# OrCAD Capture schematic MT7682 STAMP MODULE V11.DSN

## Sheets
1 10_BB_RF: size C; title: MT7682 Stamp Module; rev: 1.1; company: MediaTek Inc.; note: 10_BB_RF
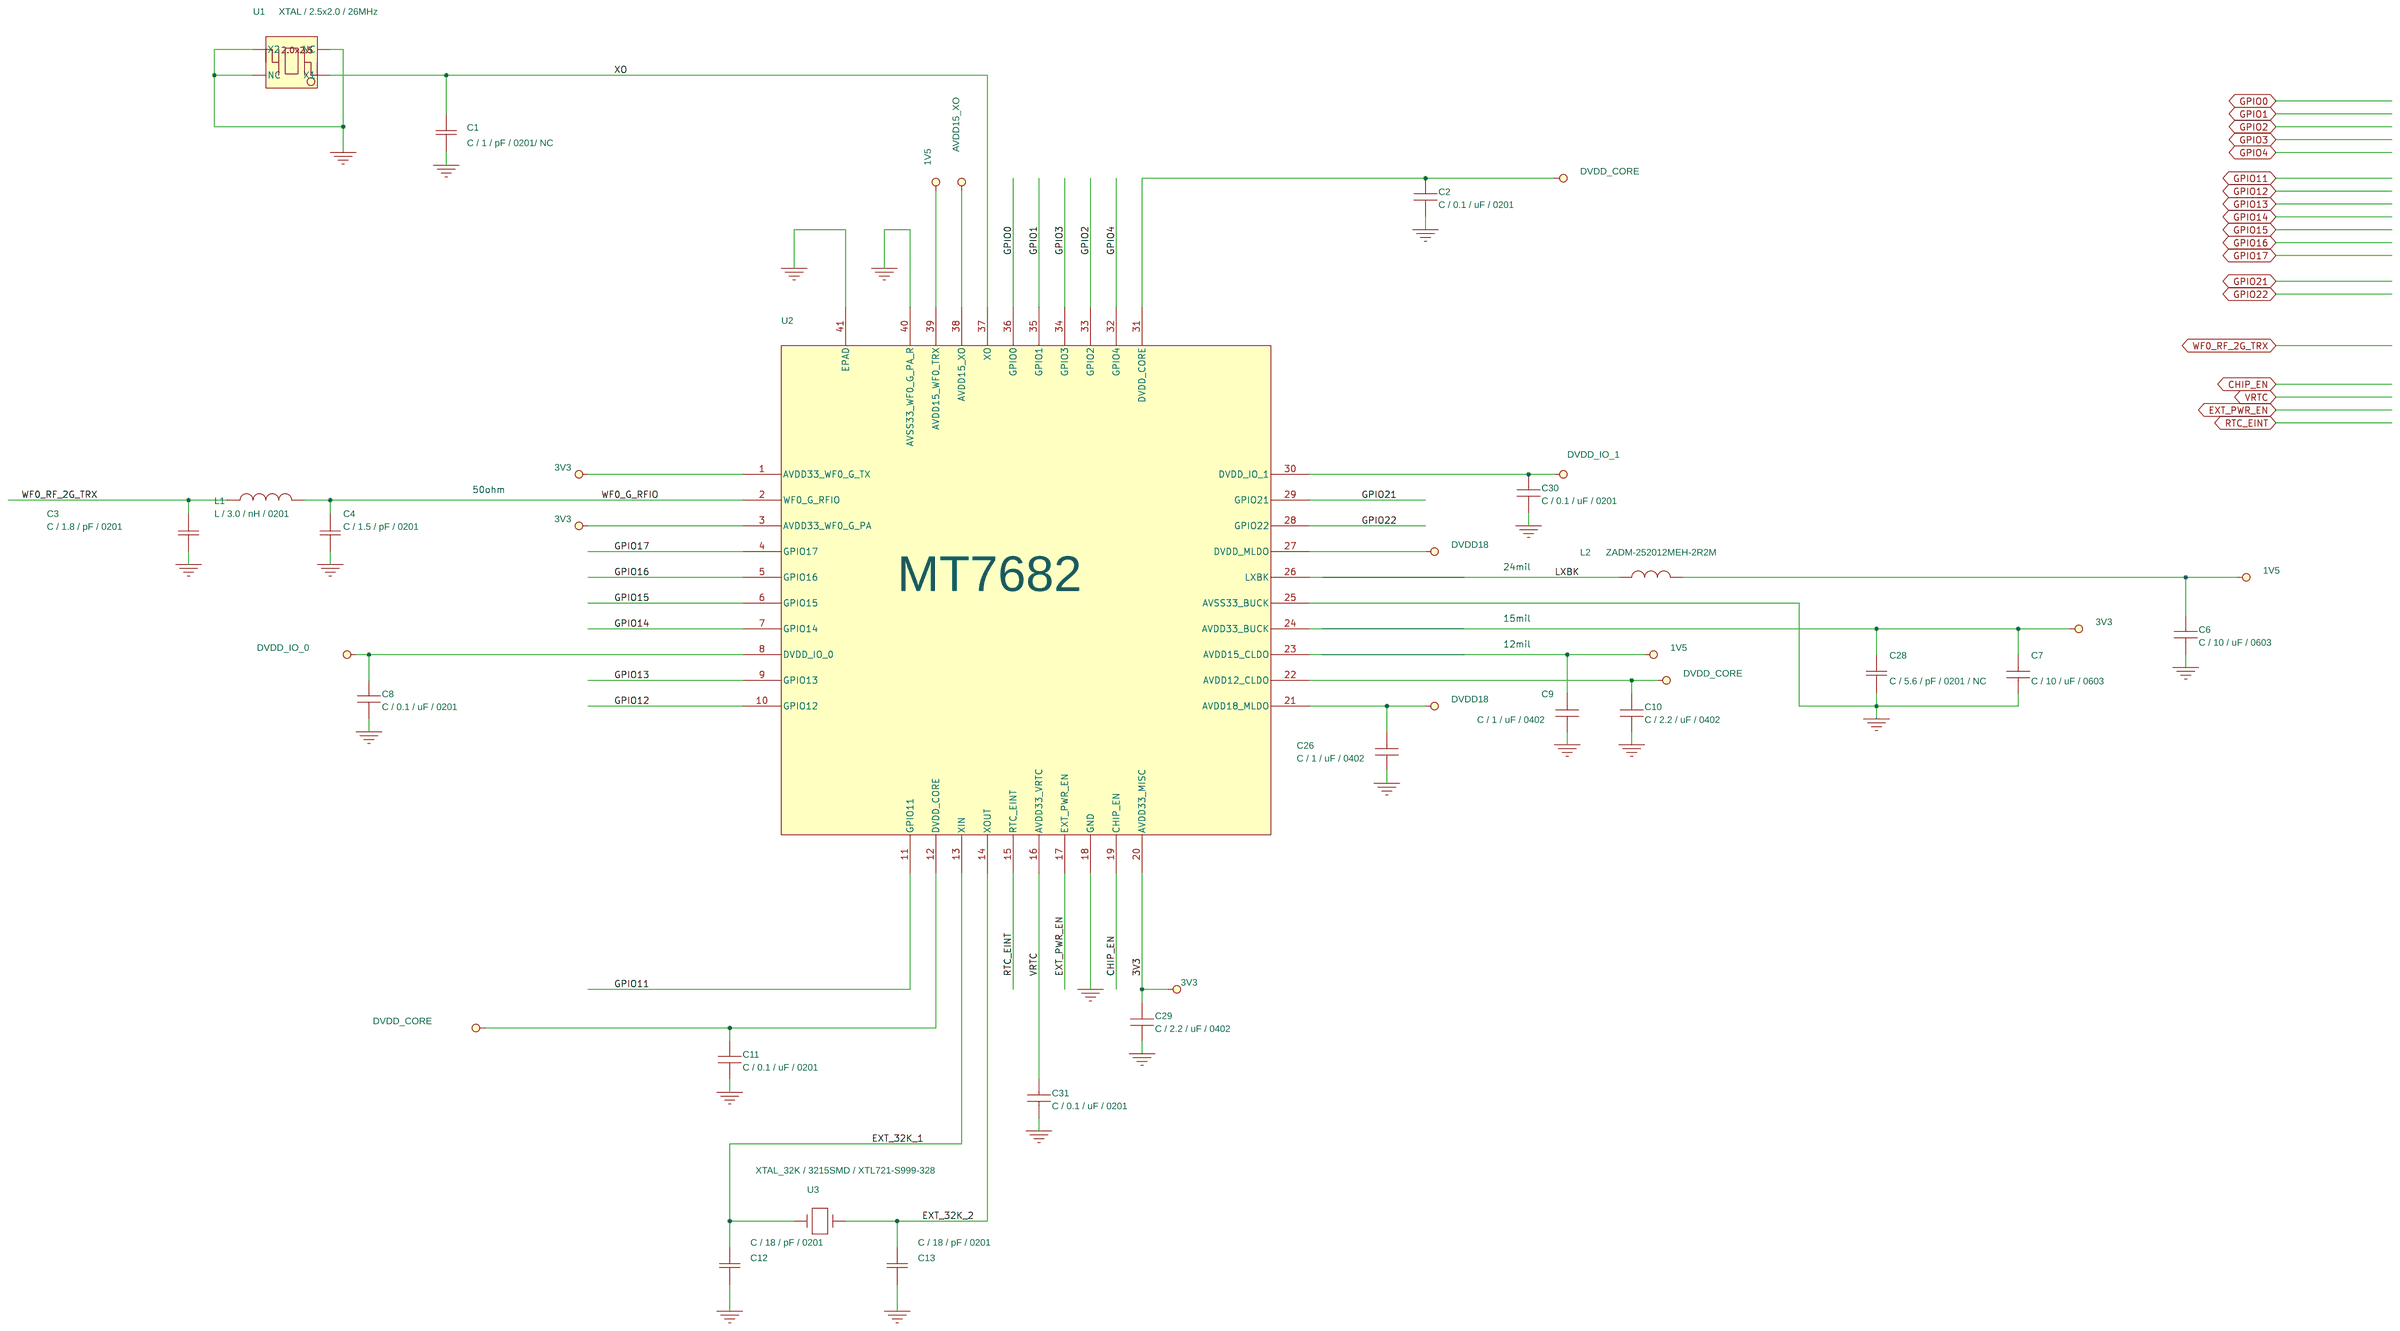
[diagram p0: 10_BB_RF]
2 20_RF Antenna and Connector: size C; note: 20_RF Antenna and Connector
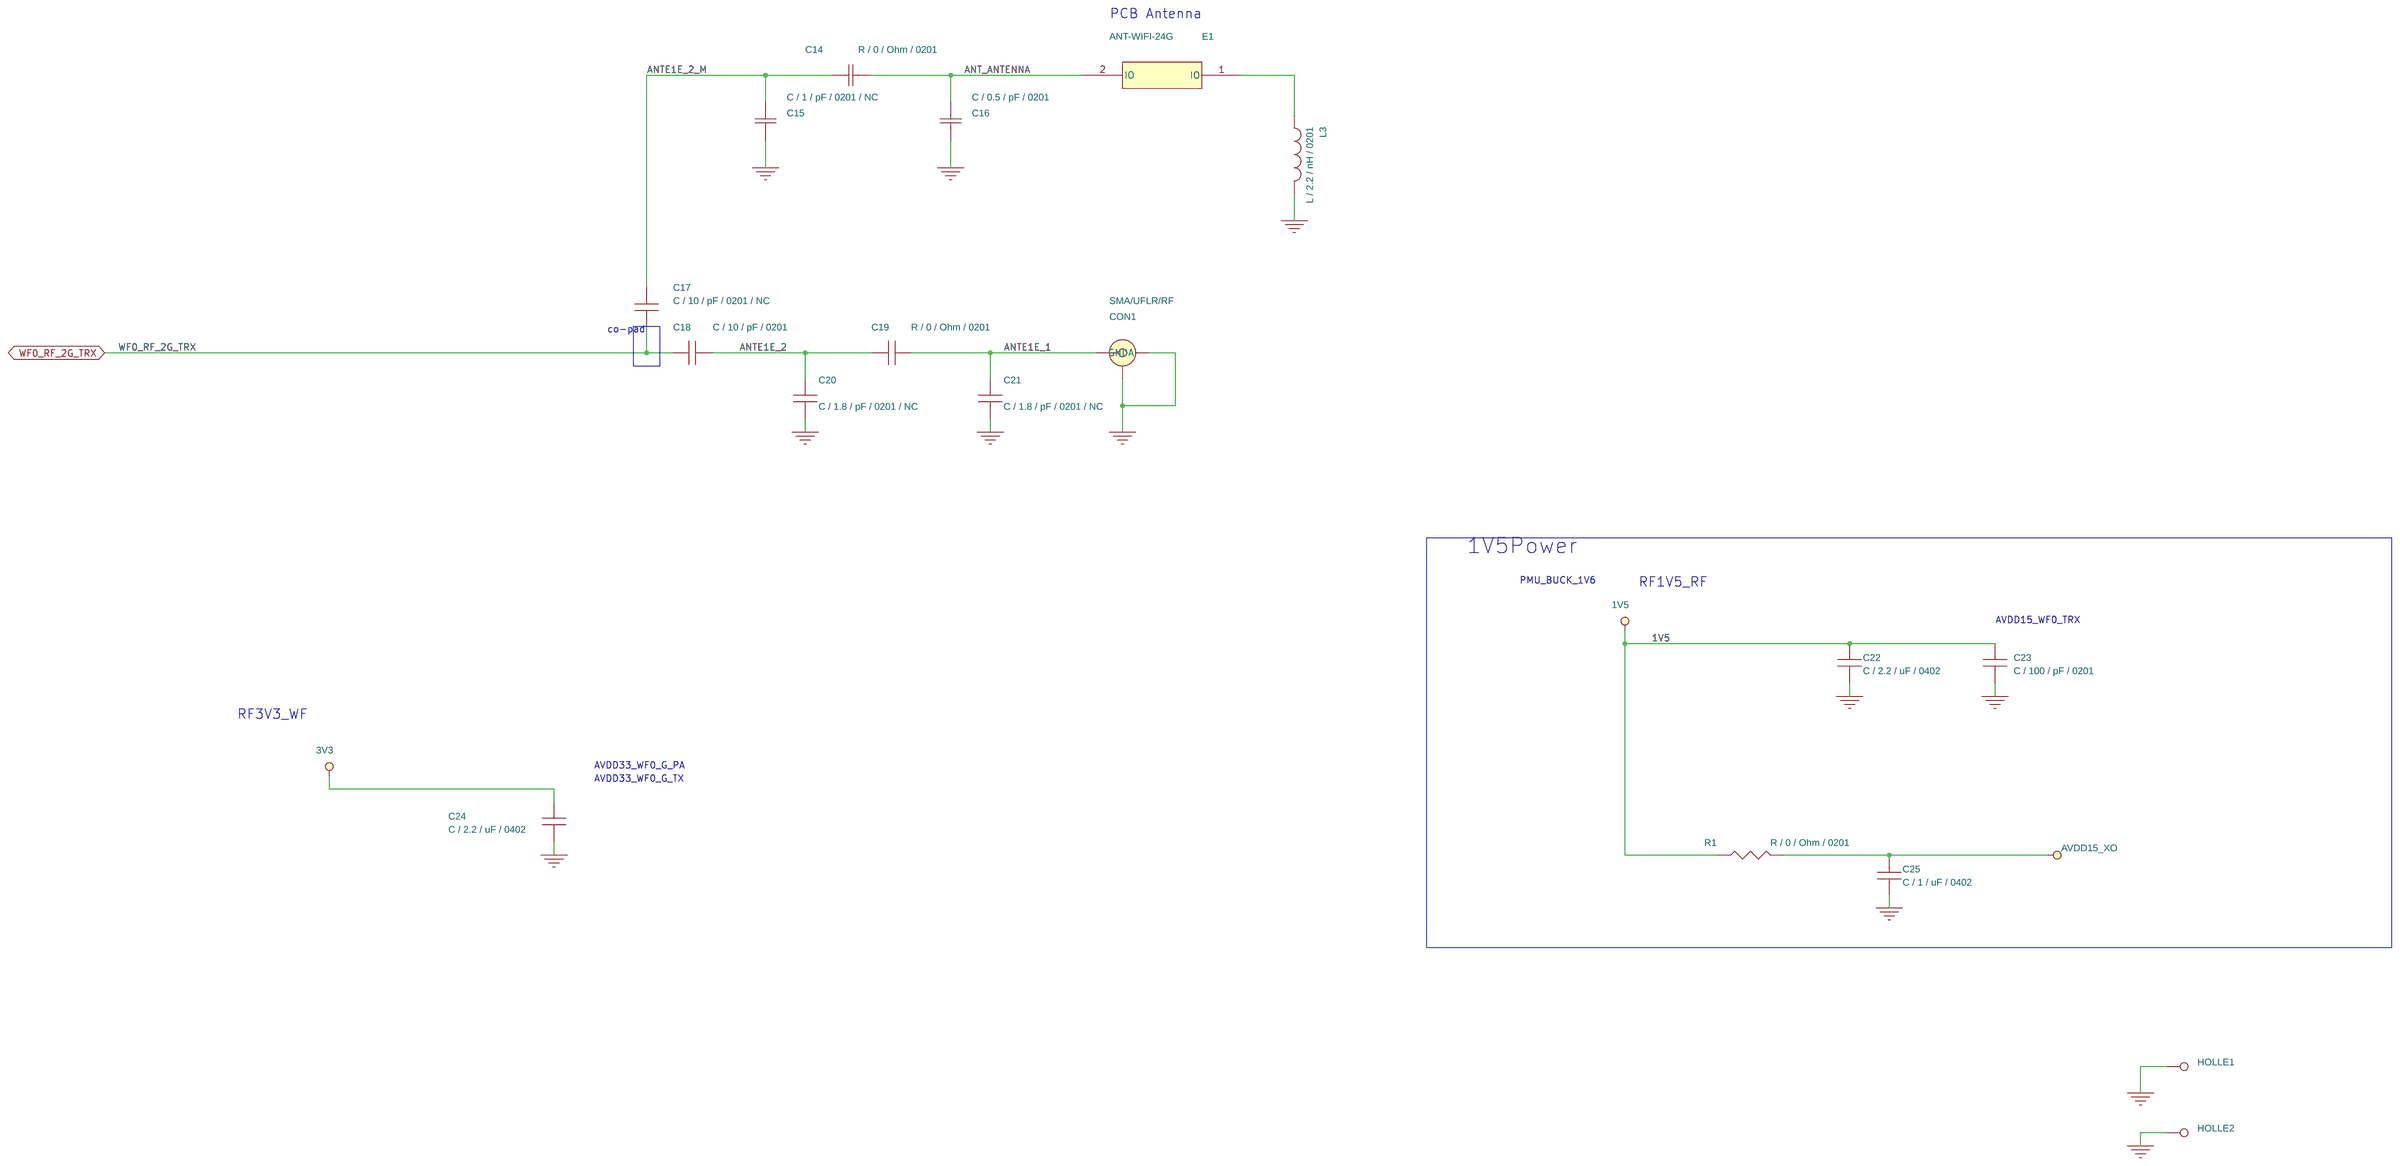
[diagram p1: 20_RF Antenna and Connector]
3 21_Strap and Module: size C; note: 21_Strap and Module
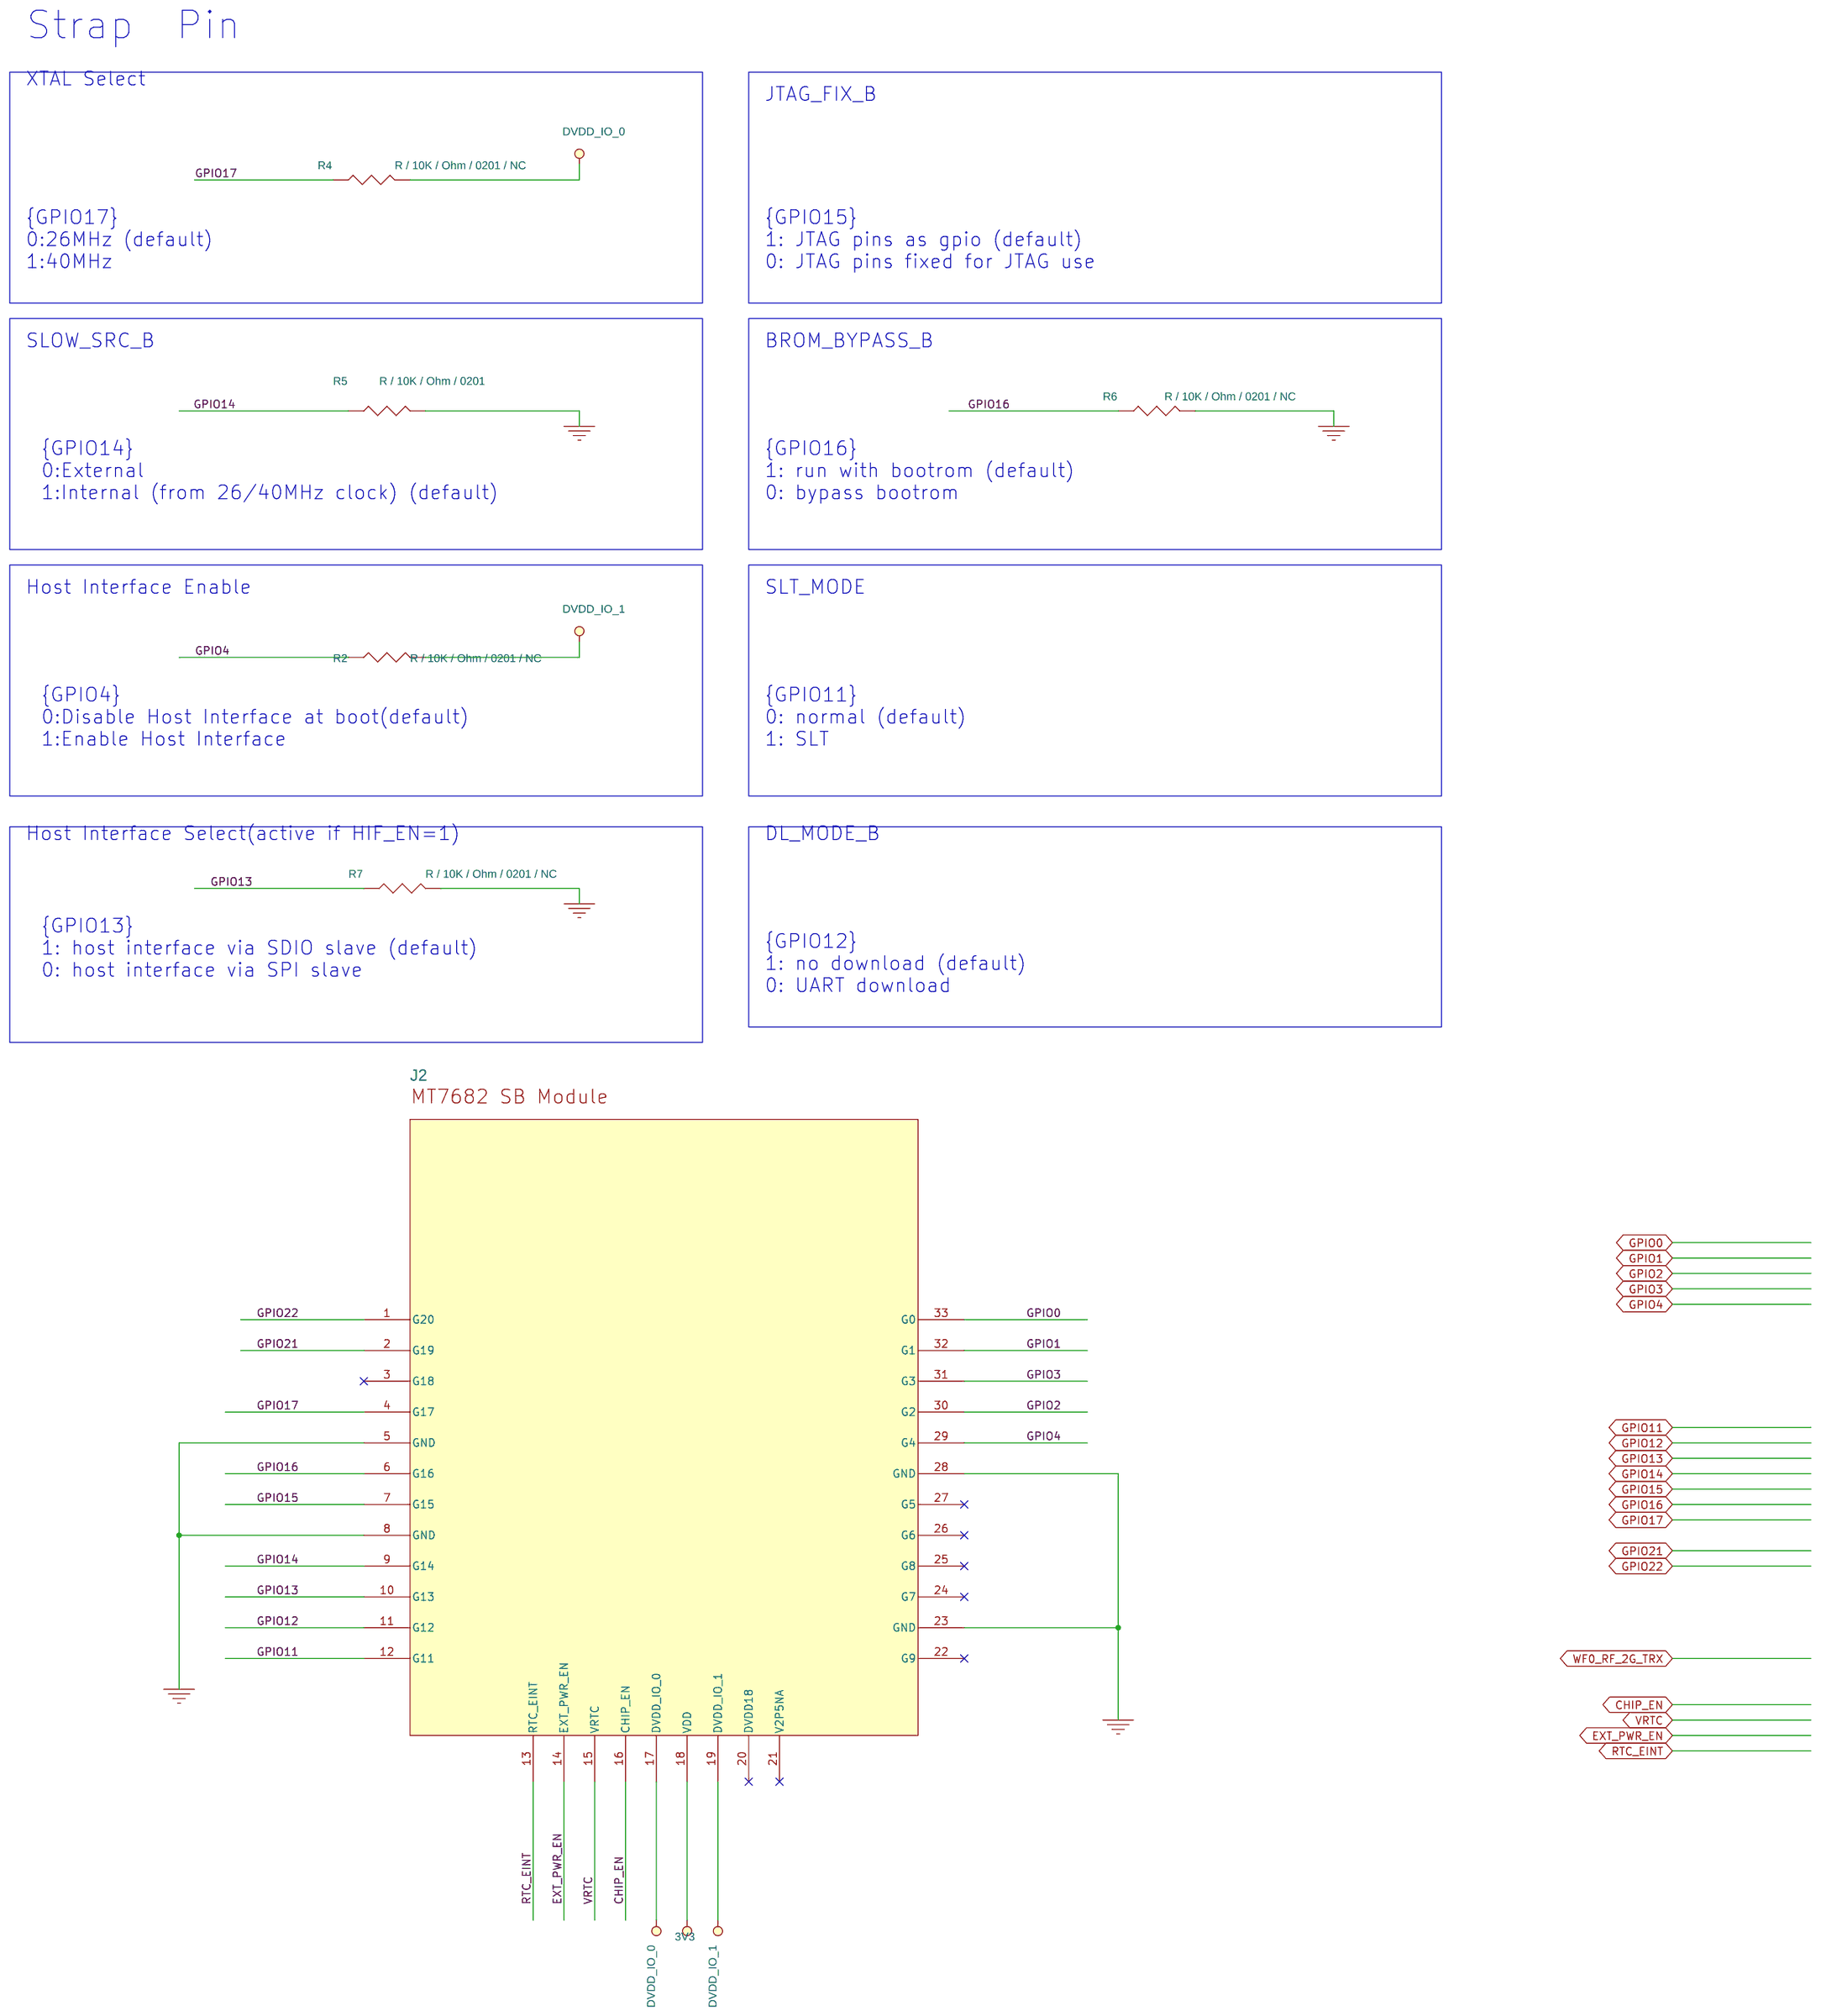
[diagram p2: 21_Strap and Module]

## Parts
sheet 10_BB_RF
C1  C / 1 / pF / 0201/ NC  [C0201]
C2  C / 0.1 / uF / 0201  [C0201]
C3  C / 1.8 / pF / 0201  [C0201]
C4  C / 1.5 / pF / 0201  [C0201]
C6  C / 10 / uF / 0603  [C0603]
C7  C / 10 / uF / 0603  [C0603]
C8  C / 0.1 / uF / 0201  [C0201]
C9  C / 1 / uF / 0402  [C0402]
C10  C / 2.2 / uF / 0402  [C0402]
C11  C / 0.1 / uF / 0201  [C0201]
C12  C / 18 / pF / 0201  [C0201]
C13  C / 18 / pF / 0201  [C0201]
C26  C / 1 / uF / 0402  [C0402]
C28  C / 5.6 / pF / 0201 / NC  [C0201]
C29  C / 2.2 / uF / 0402  [C0402]
C30  C / 0.1 / uF / 0201  [C0201]
C31  C / 0.1 / uF / 0201  [C0201]
L1  L / 3.0 / nH / 0201  [L0201]
L2  ZADM-252012MEH-2R2M  [L/IND/SMD/VLS252012E]
U1  XTAL / 2.5x2.0 / 26MHz  [CRYS/SMD/2.5X2.0/CT2520DB/KYOCERA]
U2  MT7682  [MT7682/SQFN40/P0.4/SMD/5X5]
U3  XTAL_32K / 3215SMD / XTL721-S999-328  [RTC/SMD/2P/3.2X1.5]
sheet 20_RF Antenna and Connector
C14  R / 0 / Ohm / 0201  [C0201]
C15  C / 1 / pF / 0201 / NC  [C0201]
C16  C / 0.5 / pF / 0201  [C0201]
C17  C / 10 / pF / 0201 / NC  [C0201]
C18  C / 10 / pF / 0201  [C0201]
C19  R / 0 / Ohm / 0201  [C0201]
C20  C / 1.8 / pF / 0201 / NC  [C0201]
C21  C / 1.8 / pF / 0201 / NC  [C0201]
C22  C / 2.2 / uF / 0402  [C0402]
C23  C / 100 / pF / 0201  [C0201]
C24  C / 2.2 / uF / 0402  [C0402]
C25  C / 1 / uF / 0402  [C0402]
CON1  SMA/UFLR/RF  [COAXIAL/SMD/CON/V/I-PEX]
E1  ANT-WIFI-24G  [ANT/2P/SMD/MT7682/RF_1]
HOLLE1  TP-SMD  [HOLE/PTH/R1X1.5D0.6]
HOLLE2  TP-SMD  [HOLE/PTH/R1X1.5D0.6]
L3  L / 2.2 / nH / 0201  [L0201]
R1  R / 0 / Ohm / 0201  [R0201]
sheet 21_Strap and Module
J2  pin to pin module  [MODULE/33P/SMD/MT7682]
R2  R / 10K / Ohm / 0201 / NC  [R0201]
R4  R / 10K / Ohm / 0201 / NC  [R0201]
R5  R / 10K / Ohm / 0201  [R0201]
R6  R / 10K / Ohm / 0201 / NC  [R0201]
R7  R / 10K / Ohm / 0201 / NC  [R0201]

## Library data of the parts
C1 C3 C4 C12-C16 C28 = CAP_0402
C2 C6 C8 C11 C22-C24 C30 C31 = CAPACITOR_NON-POL: PART_NUMBER: C21-0402M104Y1EWLS; PART_TYPE: C21
C7 C9 C10 C25 C26 C29 = C_0402
L1 L3 = INDUCTOR: PART_NUMBER: L42-0201S3N320ACX0; PART_TYPE: L42
L2 = L_2.5*2.0
U1 = XTAL_2.5
U2 = MT7662E-20121128_11
U3 = XTAL_49_U-SMD
C17-C19 = CAPACITOR_NON-POL: PART_NUMBER: C21-0201C3R9C1HTDK; PART_TYPE: C21
C20 = CAPACITOR_NON-POL: PART_NUMBER: C21-0201BR30C1HTDK; PART_TYPE: C21
C21 = CAPACITOR_NON-POL: PART_NUMBER: C21-0201BR30C1HTDK
CON1 = SMA_UFLR
E1 = ANT-25G-R-CB_0
HOLLE1 HOLLE2 = TP-SMD
R1 R2 R4-R7 = RESISTOR: PART_NUMBER: R31-0201J1003FWLS0; PART_TYPE: R31
J2 = S500_6

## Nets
1V5: C6.1 C9.2 C22.1 C23.1 L2.2 R1.2 U2.23(AVDD15_CLDO) U2.39(AVDD15_WF0_TRX)
3V3: C7.2 C24.1 C28.1 C29.2 J2.18(VDD) U2.1(AVDD33_WF0_G_TX) U2.3(AVDD33_WF0_G_PA) U2.20(AVDD33_MISC) U2.24(AVDD33_BUCK)
AVDD15_XO: C25.2 R1.1 U2.38(AVDD15_XO)
DVDD18: C26.2 U2.21(AVDD18_MLDO) U2.27(DVDD_MLDO)
DVDD_CORE: C2.1 C10.2 C11.1 U2.12(DVDD_CORE) U2.22(AVDD12_CLDO) U2.31(DVDD_CORE)
DVDD_IO_0: C8.1 J2.17(DVDD_IO_0) R4.1 U2.8(DVDD_IO_0)
DVDD_IO_1: C30.1 J2.19(DVDD_IO_1) R2.1 U2.30(DVDD_IO_1)
GND: C1.2 C2.2 C3.1 C4.1 C6.2 C7.1 C8.2 C9.1 C10.1 C11.2 C12.2 C13.2 C15.2 C16.2 C20.2 C21.2 C22.2 C23.2 C24.2 C25.1 C26.1 C28.2 C29.1 C30.2 C31.2 CON1.2 CON1.3(GNDA) HOLLE1.1 HOLLE2.1 J2.5(GND) J2.8(GND) J2.23(GND) J2.28(GND) L3.1 R5.1 R6.1 R7.1 U1.2(NC) U1.3(X2) U1.4(NC) U2.18(GND) U2.25(AVSS33_BUCK) U2.40(AVSS33_WF0_G_PA_R) U2.41(EPAD)
ANT_ANTENNA: C14.2 C16.1 E1.2(IO)
ANTE1E_1: C19.1 C21.1 CON1.1
ANTE1E_2: C18.2 C19.2 C20.1
ANTE1E_2_M: C14.1 C15.1 C17.2
CHIP_EN: J2.16(CHIP_EN) U2.19(CHIP_EN)
EXT_32K_1: C12.1 U2.13(XIN) U3.1
EXT_32K_2: C13.1 U2.14(XOUT) U3.2
EXT_PWR_EN: J2.14(EXT_PWR_EN) U2.17(EXT_PWR_EN)
GPIO0: J2.33(G0) U2.36(GPIO0)
GPIO1: J2.32(G1) U2.35(GPIO1)
GPIO2: J2.30(G2) U2.33(GPIO2)
GPIO3: J2.31(G3) U2.34(GPIO3)
GPIO4: J2.29(G4) R2.2 U2.32(GPIO4)
GPIO11: J2.12(G11) U2.11(GPIO11)
GPIO12: J2.11(G12) U2.10(GPIO12)
GPIO13: J2.10(G13) R7.2 U2.9(GPIO13)
GPIO14: J2.9(G14) R5.2 U2.7(GPIO14)
GPIO15: J2.7(G15) U2.6(GPIO15)
GPIO16: J2.6(G16) R6.2 U2.5(GPIO16)
GPIO17: J2.4(G17) R4.2 U2.4(GPIO17)
GPIO21: J2.2(G19) U2.29(GPIO21)
GPIO22: J2.1(G20) U2.28(GPIO22)
LXBK: L2.1 U2.26(LXBK)
RTC_EINT: J2.13(RTC_EINT) U2.15(RTC_EINT)
VRTC: C31.1 J2.15(VRTC) U2.16(AVDD33_VRTC)
WF0_G_RFIO: C4.2 L1.1 U2.2(WF0_G_RFIO)
WF0_RF_2G_TRX: C3.2 C17.1 C18.1 L1.2
XO: C1.1 U1.1(X1) U2.37(XO)
N03667: E1.1(IO) L3.2

Not connected (* = marked no-connect by the designer): J2 3(G18)* 20(DVDD18)* 21(V2P5NA)* 22(G9)* 24(G7)* 25(G8)* 26(G6)* 27(G5)*

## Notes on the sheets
sheet 1
- 50ohm
- 24mil
- 15mil
- 12mil
sheet 2
- PCB Antenna
- co-pad
- 1V5Power
- PMU_BUCK_1V6
- RF1V5_RF
- AVDD15_WF0_TRX
- RF3V3_WF
- AVDD33_WF0_G_PA
- AVDD33_WF0_G_TX
sheet 3
- Strap  Pin
- XTAL Select
- JTAG_FIX_B
- {GPIO17}
  0:26MHz (default)
  1:40MHz
- {GPIO15}
  1: JTAG pins as gpio (default)
  0: JTAG pins fixed for JTAG use
- SLOW_SRC_B
- BROM_BYPASS_B
- {GPIO14}
  0:External
  1:Internal (from 26/40MHz clock) (default)
- {GPIO16}
  1: run with bootrom (default)
  0: bypass bootrom
- Host Interface Enable
- SLT_MODE
- {GPIO4}
  0:Disable Host Interface at boot(default)
  1:Enable Host Interface
- {GPIO11}
  0: normal (default)
  1: SLT
- Host Interface Select(active if HIF_EN=1)
- DL_MODE_B
- {GPIO13}
  1: host interface via SDIO slave (default)
  0: host interface via SPI slave
- {GPIO12}
  1: no download (default)
  0: UART download
